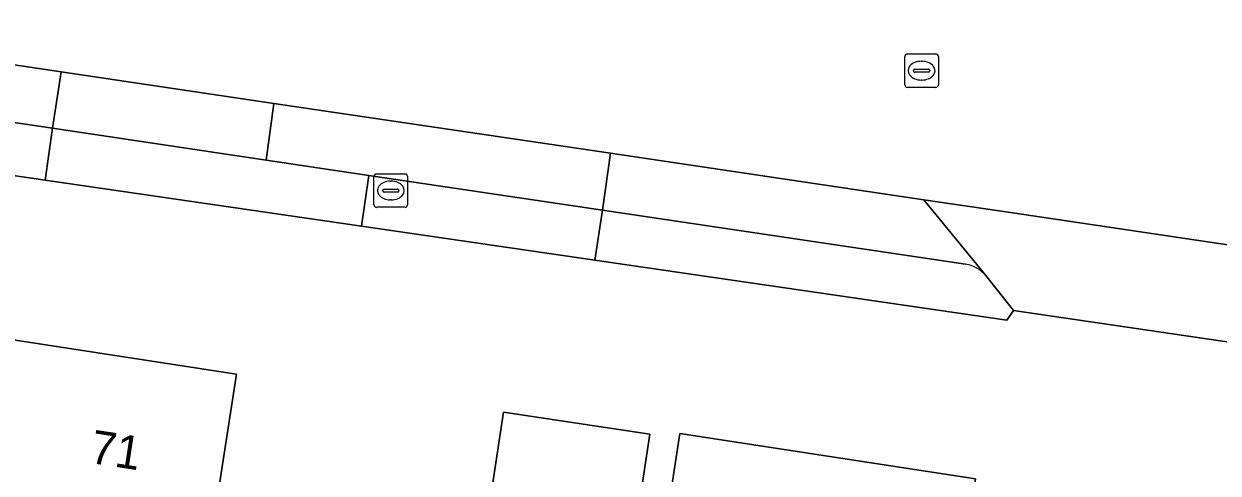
# Model space of a CAD drawing. Extents: x 163683 to 164494, y 382709 to 383872.
# Drawn here: x 163841.46 to 163877.1, y 382929.41 to 382942.82 of the extents above; entities that cross this region are included whole.
import ezdxf

# ---------------------------------------------------------------- set-up
doc = ezdxf.new("R2010")
doc.units = 0
for name, color, linetype in [('IMGEO_Brandkraan', 7, 'Continuous'), ('IMGEO_Erf', 7, 'Continuous'), ('IMGEO_Pand', 7, 'Continuous'), ('IMGEO_Pand_nummerreeks', 7, 'Continuous'), ('IMGEO_Parkeervlak_open', 7, 'Continuous'), ('IMGEO_Rijbaan_lokaal_gesloten', 7, 'Continuous'), ('IMGEO_Rioolput', 7, 'Continuous'), ('IMGEO_Voetpad_open', 7, 'Continuous')]:
    doc.layers.add(name, color=color, linetype=linetype)

msp = doc.modelspace()

# ---------------------------------------------------------------- linework, layer by layer
at = {"layer": 'IMGEO_Brandkraan'}
for p, q in [((163851.906, 382937.415), (163851.906, 382938.267)), ((163851.981, 382938.341), (163852.833, 382938.341)), ((163852.394, 382938.121), (163852.419, 382938.121)), ((163852.907, 382938.267), (163852.907, 382937.415)), ((163852.165, 382937.835), (163852.165, 382937.847)), ((163852.603, 382937.798), (163852.205, 382937.798)), ((163852.208, 382937.884), (163852.606, 382937.884)), ((163852.649, 382937.847), (163852.649, 382937.835)), ((163852.833, 382937.341), (163851.981, 382937.341)), ((163852.417, 382937.561), (163852.392, 382937.561))]:
    msp.add_line(p, q, dxfattribs=at)
for points in [[(163851.906, 382937.415), (163851.906, 382938.267)], [(163851.981, 382938.341), (163852.833, 382938.341)], [(163852.907, 382938.267), (163852.907, 382937.415)], [(163852.833, 382937.341), (163851.981, 382937.341)]]:
    msp.add_lwpolyline(points, dxfattribs=at)
for centre, radius, start, end in [((163851.983, 382938.265), 0.0765, 91.552, 178.448), ((163851.983, 382938.265), 0.0765, 91.552, 178.448), ((163852.831, 382938.265), 0.0765, 1.552, 88.448), ((163852.831, 382938.265), 0.0765, 1.552, 88.448), ((163852.205, 382937.844), 0.0403, 85.8775, 175.7526), ((163852.202, 382937.834), 0.0366, 178.938, 274.7102), ((163852.606, 382937.841), 0.043, 264.8664, 352.4533), ((163852.61, 382937.846), 0.0386, 1.7309, 96.639), ((163851.983, 382937.417), 0.0765, 181.552, 268.448), ((163851.983, 382937.417), 0.0765, 181.552, 268.448), ((163852.831, 382937.417), 0.0765, 271.552, 358.448), ((163852.831, 382937.417), 0.0765, 271.552, 358.448)]:
    msp.add_arc(centre, radius, start, end, dxfattribs=at)
for centre, major_axis, ratio, start_param, end_param in [((163852.393, 382937.841), (-0.387, 0.002), 0.722429, 4.712389, 7.853982), ((163852.418, 382937.841), (-0.39, 0.002), 0.717154, 1.570796, 4.712389)]:
    msp.add_ellipse(centre, major_axis=major_axis, ratio=ratio, start_param=start_param, end_param=end_param, dxfattribs=at)
at = {"layer": 'IMGEO_Erf'}
msp.add_lwpolyline([(163906.226, 382929.097), (163890.649, 382931.381), (163882.719, 382932.544), (163870.994, 382934.264), (163870.789, 382933.974), (163858.502, 382935.761), (163851.533, 382936.775), (163842.096, 382938.147), (163836.962, 382938.894), (163823.096, 382940.911), (163822.429, 382936.108), (163830.344, 382934.912), (163825.387, 382900.945)], dxfattribs=at)
for points in [[(163847.041, 382927.417), (163846.534, 382924.125), (163840.131, 382925.111), (163839.169, 382925.259), (163840.427, 382933.415), (163840.439, 382933.493), (163841.4, 382933.345), (163847.803, 382932.358)], [(163858.91, 382922.412), (163854.541, 382923.07), (163855.769, 382931.233), (163860.138, 382930.575)], [(163868.785, 382922.291), (163862.622, 382923.241), (163862.124, 382920.011), (163865.069, 382919.557), (163863.838, 382911.569), (163858.237, 382912.432), (163860.275, 382925.653), (163861.036, 382930.594), (163869.855, 382929.235), (163869.094, 382924.294)]]:
    msp.add_lwpolyline(points, close=True, dxfattribs=at)
at = {"layer": 'IMGEO_Pand'}
for points in [[(163847.041, 382927.417), (163847.803, 382932.358), (163841.4, 382933.345), (163840.439, 382933.493), (163840.427, 382933.415), (163839.169, 382925.259), (163840.131, 382925.111), (163846.534, 382924.125)], [(163858.91, 382922.412), (163860.138, 382930.575), (163855.769, 382931.233), (163854.541, 382923.07)], [(163869.094, 382924.294), (163869.855, 382929.235), (163861.036, 382930.594), (163860.275, 382925.653), (163858.237, 382912.432), (163863.838, 382911.569), (163865.069, 382919.557), (163862.124, 382920.011), (163862.622, 382923.241), (163868.785, 382922.291)]]:
    msp.add_lwpolyline(points, close=True, dxfattribs=at)
at = {"layer": 'IMGEO_Parkeervlak_open'}
msp.add_lwpolyline([(163848.912, 382940.443), (163842.566, 382941.383), (163842.309, 382939.7), (163848.693, 382938.75)], close=True, dxfattribs=at)
for points in [[(163868.32, 382937.568), (163858.966, 382938.954), (163858.729, 382937.257), (163869.562, 382935.646)], [(163870.17, 382935.305), (163868.32, 382937.568)]]:
    msp.add_lwpolyline(points, dxfattribs=at)
msp.add_arc((163869.389, 382934.626), 1.035, 41.032, 80.3957, dxfattribs=at)
at = {"layer": 'IMGEO_Rijbaan_lokaal_gesloten'}
msp.add_lwpolyline([(163721.918, 382959.161), (163746.267, 382955.645), (163746.439, 382955.62), (163814.345, 382945.562), (163823.903, 382944.146), (163837.413, 382942.146), (163842.566, 382941.383), (163848.912, 382940.443), (163858.966, 382938.954), (163868.32, 382937.568), (163870.569, 382937.235), (163884.955, 382935.095), (163891.024, 382934.192), (163906.594, 382931.876), (163906.556, 382931.624), (163919.071, 382929.775), (163929.575, 382928.223)], dxfattribs=at)
at = {"layer": 'IMGEO_Rioolput'}
for p, q in [((163867.749, 382940.994), (163867.749, 382941.846)), ((163867.824, 382941.92), (163868.676, 382941.92)), ((163868.237, 382941.7), (163868.262, 382941.7)), ((163868.75, 382941.846), (163868.75, 382940.994)), ((163868.008, 382941.414), (163868.008, 382941.426)), ((163868.446, 382941.377), (163868.048, 382941.377)), ((163868.051, 382941.463), (163868.449, 382941.463)), ((163868.492, 382941.426), (163868.492, 382941.414)), ((163868.676, 382940.92), (163867.824, 382940.92)), ((163868.26, 382941.14), (163868.235, 382941.14))]:
    msp.add_line(p, q, dxfattribs=at)
for points in [[(163867.749, 382940.994), (163867.749, 382941.846)], [(163867.824, 382941.92), (163868.676, 382941.92)], [(163868.75, 382941.846), (163868.75, 382940.994)], [(163868.676, 382940.92), (163867.824, 382940.92)]]:
    msp.add_lwpolyline(points, dxfattribs=at)
for centre, radius, start, end in [((163867.826, 382941.844), 0.0765, 91.552, 178.448), ((163867.826, 382941.844), 0.0765, 91.552, 178.448), ((163868.674, 382941.844), 0.0765, 1.552, 88.448), ((163868.674, 382941.844), 0.0765, 1.552, 88.448), ((163868.048, 382941.423), 0.0403, 85.8775, 175.7526), ((163868.045, 382941.413), 0.0366, 178.938, 274.7102), ((163868.449, 382941.42), 0.043, 264.8664, 352.4533), ((163868.453, 382941.425), 0.0386, 1.7309, 96.639), ((163867.826, 382940.996), 0.0765, 181.552, 268.448), ((163867.826, 382940.996), 0.0765, 181.552, 268.448), ((163868.674, 382940.996), 0.0765, 271.552, 358.448), ((163868.674, 382940.996), 0.0765, 271.552, 358.448)]:
    msp.add_arc(centre, radius, start, end, dxfattribs=at)
for centre, major_axis, ratio, start_param, end_param in [((163868.236, 382941.42), (-0.387, 0.002), 0.722429, 4.712389, 7.853982), ((163868.261, 382941.42), (-0.39, 0.002), 0.717154, 1.570796, 4.712389)]:
    msp.add_ellipse(centre, major_axis=major_axis, ratio=ratio, start_param=start_param, end_param=end_param, dxfattribs=at)
at = {"layer": 'IMGEO_Voetpad_open'}
for points in [[(163842.566, 382941.383), (163837.413, 382942.146), (163837.17, 382940.464), (163842.309, 382939.7)], [(163842.309, 382939.7), (163837.17, 382940.464), (163836.962, 382938.894), (163842.096, 382938.147)], [(163858.966, 382938.954), (163848.912, 382940.443), (163848.693, 382938.75), (163851.752, 382938.295), (163858.729, 382937.257)], [(163848.693, 382938.75), (163842.309, 382939.7), (163842.096, 382938.147), (163851.533, 382936.775), (163851.752, 382938.295)], [(163858.729, 382937.257), (163851.752, 382938.295), (163851.533, 382936.775), (163858.502, 382935.761)], [(163884.955, 382935.095), (163870.569, 382937.235), (163868.32, 382937.568), (163870.17, 382935.305), (163870.994, 382934.264), (163882.719, 382932.544)]]:
    msp.add_lwpolyline(points, close=True, dxfattribs=at)
msp.add_lwpolyline([(163869.562, 382935.646), (163858.729, 382937.257), (163858.502, 382935.761), (163870.789, 382933.974), (163870.994, 382934.264), (163870.17, 382935.305)], dxfattribs=at)
msp.add_arc((163869.389, 382934.626), 1.035, 41.032, 80.3957, dxfattribs=at)

# ---------------------------------------------------------------- texts
at = {"layer": 'IMGEO_Pand_nummerreeks'}
msp.add_text('71', height=1, rotation=351.2395, dxfattribs=at).set_placement((163843.397, 382929.719))

doc.saveas('drawing.dxf')
